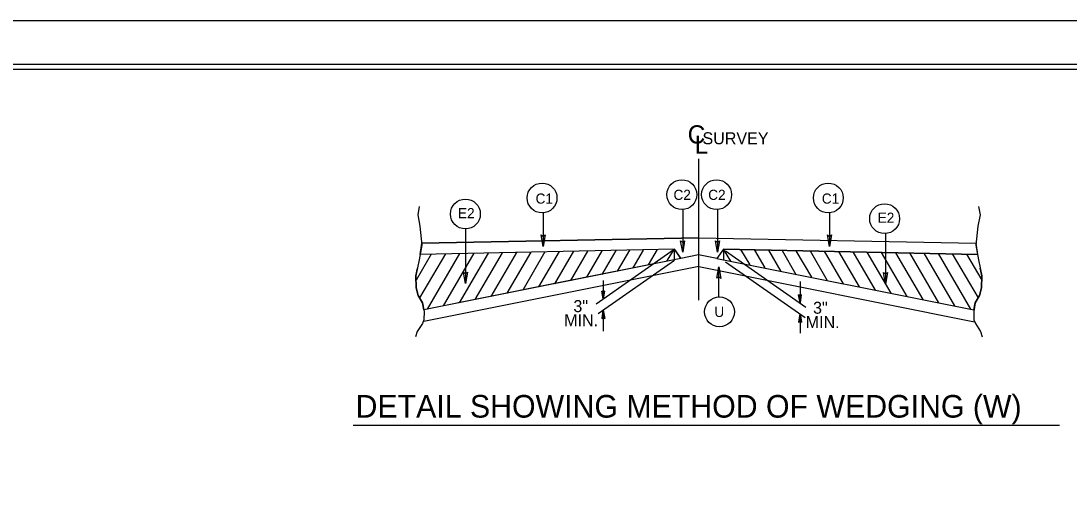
# Model space of a CAD drawing. Extents: x 1542177 to 1542464, y 45134 to 45344.
# Drawn here: x 1542284.79 to 1542327.96, y 45308.47 to 45328.62 of the extents above; entities that cross this region are included whole.
import ezdxf

# ---------------------------------------------------------------- set-up
doc = ezdxf.new("R2010")
doc.units = 0
for name, color, linetype in [('Prop Dimension', 7, 'Continuous'), ('Prop Dimension Text', 7, 'Continuous'), ('Sheet Cutting Line CELL', 7, 'Continuous'), ('Sheet Plot Border Inside CELL', 7, 'Continuous'), ('Sheet Plot Border Outside CELL', 7, 'Continuous'), ('Sheet Typical CELL', 7, 'Continuous'), ('Typical Detail Wedge2 CELL', 7, 'Continuous'), ('Typical ID Circle CELL', 7, 'Continuous'), ('Typical Terminator CELL', 7, 'Continuous'), ('Typical Text Centerline CELL', 7, 'Continuous'), ('Typical Text ID Circle CELL', 7, 'Continuous'), ('Typical Text Label CELL', 7, 'Continuous')]:
    doc.layers.add(name, color=color, linetype=linetype)

msp = doc.modelspace()

# ---------------------------------------------------------------- linework, layer by layer
at = {"layer": 'Prop Dimension'}
msp.add_line((1542312.711, 45317.117), (1542312.711, 45322.933), dxfattribs=at)
for centre in [(1542306.253, 45321.323), (1542312.011, 45321.459), (1542313.441, 45321.459), (1542318.042, 45321.323), (1542303.095, 45320.662), (1542320.361, 45320.47), (1542313.559, 45316.631)]:
    msp.add_circle(centre, 0.615, dxfattribs=at)
at = {"layer": 'Prop Dimension Text'}
msp.add_line((1542298.473, 45311.958), (1542327.56, 45311.958), dxfattribs=at)
at = {"layer": 'Sheet Cutting Line CELL'}
msp.add_line((1542360.727, 45328.616), (1542226.007, 45328.616), dxfattribs=at)
at = {"layer": 'Sheet Plot Border Inside CELL'}
msp.add_lwpolyline([(1542360.367, 45326.82), (1542227.047, 45326.82), (1542227.047, 45242.412), (1542360.367, 45242.412)], close=True, dxfattribs=at)
at = {"layer": 'Sheet Plot Border Outside CELL'}
for points in [[(1542360.727, 45328.616), (1542226.007, 45328.616), (1542226.007, 45240.616), (1542360.727, 45240.616)], [(1542360.727, 45328.615), (1542226.007, 45328.615), (1542226.007, 45240.616), (1542360.727, 45240.616)]]:
    msp.add_lwpolyline(points, close=True, dxfattribs=at)
at = {"layer": 'Sheet Typical CELL'}
msp.add_lwpolyline([(1542359.367, 45326.616), (1542239.367, 45326.616), (1542239.367, 45242.616), (1542359.367, 45242.616)], close=True, dxfattribs=at)
at = {"layer": 'Typical Detail Wedge2 CELL'}
for p, q in [((1542312.711, 45317.117), (1542312.711, 45321.089)), ((1542301.232, 45319), (1542301.297, 45319.458)), ((1542312.711, 45319.686), (1542301.297, 45319.458)), ((1542301.297, 45319.458), (1542312.711, 45319.686)), ((1542312.711, 45319.686), (1542324.125, 45319.458)), ((1542312.712, 45319.686), (1542324.125, 45319.458)), ((1542324.125, 45319.458), (1542324.191, 45319)), ((1542301.687, 45319.009), (1542301.063, 45317.939)), ((1542302.273, 45319.02), (1542301.212, 45317.203)), ((1542311.71, 45319.209), (1542301.232, 45319)), ((1542311.71, 45319.209), (1542301.232, 45319)), ((1542302.859, 45319.032), (1542301.523, 45316.743)), ((1542303.444, 45319.044), (1542302.178, 45316.874)), ((1542304.03, 45319.055), (1542302.833, 45317.005)), ((1542304.616, 45319.067), (1542303.489, 45317.136)), ((1542305.202, 45319.079), (1542304.144, 45317.267)), ((1542305.787, 45319.091), (1542304.8, 45317.398)), ((1542306.373, 45319.102), (1542305.455, 45317.529)), ((1542306.959, 45319.114), (1542306.111, 45317.66)), ((1542307.545, 45319.126), (1542306.766, 45317.792)), ((1542308.13, 45319.137), (1542307.422, 45317.923)), ((1542308.716, 45319.149), (1542308.077, 45318.054)), ((1542311.697, 45319.201), (1542308.481, 45316.948)), ((1542309.286, 45319.161), (1542308.712, 45318.175)), ((1542309.849, 45319.172), (1542309.346, 45318.308)), ((1542310.418, 45319.17), (1542309.99, 45318.439)), ((1542310.99, 45319.2), (1542310.618, 45318.562)), ((1542311.385, 45318.721), (1542311.695, 45319.205)), ((1542311.695, 45319.205), (1542311.695, 45318.807)), ((1542311.966, 45318.833), (1542311.71, 45319.209)), ((1542311.71, 45319.197), (1542311.966, 45318.833)), ((1542312.694, 45318.984), (1542311.966, 45318.833)), ((1542313.456, 45318.833), (1542312.694, 45318.984)), ((1542313.721, 45319.209), (1542313.456, 45318.833)), ((1542313.721, 45319.209), (1542313.456, 45318.833)), ((1542313.721, 45319.209), (1542324.191, 45319)), ((1542314.03, 45318.725), (1542313.721, 45319.209)), ((1542313.721, 45319.209), (1542313.721, 45318.779)), ((1542324.191, 45319), (1542313.721, 45319.209)), ((1542313.808, 45319.148), (1542317.121, 45316.828)), ((1542314.432, 45319.2), (1542314.804, 45318.562)), ((1542315.004, 45319.17), (1542315.432, 45318.439)), ((1542315.573, 45319.172), (1542316.088, 45318.288)), ((1542316.136, 45319.161), (1542316.711, 45318.175)), ((1542316.707, 45319.149), (1542317.345, 45318.054)), ((1542317.292, 45319.138), (1542318.001, 45317.923)), ((1542317.878, 45319.126), (1542318.656, 45317.792)), ((1542318.463, 45319.114), (1542319.311, 45317.661)), ((1542319.049, 45319.102), (1542319.966, 45317.53)), ((1542319.635, 45319.091), (1542320.622, 45317.398)), ((1542320.22, 45319.079), (1542321.277, 45317.267)), ((1542320.806, 45319.067), (1542321.932, 45317.136)), ((1542321.392, 45319.056), (1542322.587, 45317.005)), ((1542321.977, 45319.044), (1542323.242, 45316.874)), ((1542322.563, 45319.032), (1542323.898, 45316.743)), ((1542323.149, 45319.02), (1542324.209, 45317.202)), ((1542323.734, 45319.009), (1542324.359, 45317.937)), ((1542312.707, 45318.496), (1542301.379, 45316.23)), ((1542311.967, 45318.832), (1542301.383, 45316.715)), ((1542311.966, 45318.832), (1542306.569, 45317.752)), ((1542311.704, 45318.748), (1542308.557, 45316.544)), ((1542312.715, 45318.496), (1542324.07, 45316.225)), ((1542313.455, 45318.832), (1542324.04, 45316.715)), ((1542313.455, 45318.832), (1542324.04, 45316.715)), ((1542313.803, 45318.697), (1542317.084, 45316.4)), ((1542308.076, 45318.054), (1542307.718, 45317.982)), ((1542306.569, 45317.752), (1542301.383, 45316.715)), ((1542308.774, 45317.919), (1542308.774, 45317.154)), ((1542316.879, 45317.875), (1542316.879, 45316.998)), ((1542308.774, 45317.154), (1542308.714, 45317.489)), ((1542308.774, 45317.445), (1542308.714, 45317.489)), ((1542308.774, 45317.154), (1542308.723, 45317.483)), ((1542308.731, 45317.476), (1542308.774, 45317.154)), ((1542308.774, 45317.154), (1542308.74, 45317.471)), ((1542308.748, 45317.464), (1542308.774, 45317.154)), ((1542308.774, 45317.154), (1542308.757, 45317.458)), ((1542308.765, 45317.452), (1542308.774, 45317.154)), ((1542308.774, 45317.154), (1542308.833, 45317.489)), ((1542308.833, 45317.489), (1542308.774, 45317.445)), ((1542308.825, 45317.483), (1542308.774, 45317.154)), ((1542308.774, 45317.154), (1542308.816, 45317.476)), ((1542308.807, 45317.471), (1542308.774, 45317.154)), ((1542308.774, 45317.154), (1542308.799, 45317.464)), ((1542308.79, 45317.458), (1542308.774, 45317.154)), ((1542308.774, 45317.154), (1542308.782, 45317.452)), ((1542308.774, 45317.445), (1542308.774, 45317.154)), ((1542316.879, 45316.998), (1542316.82, 45317.333)), ((1542316.879, 45317.29), (1542316.82, 45317.333)), ((1542316.879, 45316.998), (1542316.828, 45317.327)), ((1542316.837, 45317.321), (1542316.879, 45316.998)), ((1542316.879, 45316.998), (1542316.845, 45317.314)), ((1542316.854, 45317.308), (1542316.879, 45316.998)), ((1542316.879, 45316.998), (1542316.862, 45317.302)), ((1542316.87, 45317.296), (1542316.879, 45316.998)), ((1542316.879, 45316.998), (1542316.938, 45317.333)), ((1542316.938, 45317.333), (1542316.879, 45317.29)), ((1542316.93, 45317.327), (1542316.879, 45316.998)), ((1542316.879, 45316.998), (1542316.921, 45317.321)), ((1542316.913, 45317.314), (1542316.879, 45316.998)), ((1542316.879, 45316.998), (1542316.904, 45317.308)), ((1542316.896, 45317.302), (1542316.879, 45316.998)), ((1542316.879, 45316.998), (1542316.888, 45317.296)), ((1542316.879, 45317.29), (1542316.879, 45316.998)), ((1542308.774, 45316.696), (1542308.714, 45316.36)), ((1542308.714, 45316.36), (1542308.774, 45316.404)), ((1542308.723, 45316.367), (1542308.774, 45316.696)), ((1542308.774, 45316.696), (1542308.731, 45316.373)), ((1542308.74, 45316.379), (1542308.774, 45316.696)), ((1542308.774, 45316.696), (1542308.748, 45316.385)), ((1542308.757, 45316.391), (1542308.774, 45316.696)), ((1542308.774, 45316.696), (1542308.765, 45316.397)), ((1542308.774, 45316.696), (1542308.774, 45315.834)), ((1542308.774, 45316.696), (1542308.833, 45316.36)), ((1542308.774, 45316.404), (1542308.774, 45316.696)), ((1542308.782, 45316.397), (1542308.774, 45316.696)), ((1542308.774, 45316.696), (1542308.79, 45316.391)), ((1542308.799, 45316.385), (1542308.774, 45316.696)), ((1542308.774, 45316.696), (1542308.807, 45316.379)), ((1542308.816, 45316.373), (1542308.774, 45316.696)), ((1542308.774, 45316.696), (1542308.825, 45316.367)), ((1542308.774, 45316.404), (1542308.833, 45316.36)), ((1542316.879, 45316.544), (1542316.82, 45316.208)), ((1542316.828, 45316.215), (1542316.879, 45316.544)), ((1542316.879, 45316.544), (1542316.837, 45316.221)), ((1542316.845, 45316.227), (1542316.879, 45316.544)), ((1542316.879, 45316.544), (1542316.854, 45316.233)), ((1542316.862, 45316.239), (1542316.879, 45316.544)), ((1542316.879, 45316.544), (1542316.87, 45316.245)), ((1542316.879, 45316.544), (1542316.879, 45315.759)), ((1542316.879, 45316.544), (1542316.938, 45316.208)), ((1542316.879, 45316.252), (1542316.879, 45316.544)), ((1542316.888, 45316.245), (1542316.879, 45316.544)), ((1542316.879, 45316.544), (1542316.896, 45316.239)), ((1542316.904, 45316.233), (1542316.879, 45316.544)), ((1542316.879, 45316.544), (1542316.913, 45316.227)), ((1542316.921, 45316.221), (1542316.879, 45316.544)), ((1542316.879, 45316.544), (1542316.93, 45316.215)), ((1542316.82, 45316.208), (1542316.879, 45316.252)), ((1542316.879, 45316.252), (1542316.938, 45316.208))]:
    msp.add_line(p, q, dxfattribs=at)
for points in [[(1542301.191, 45320.965), (1542301.13, 45320.63), (1542301.221, 45320.155), (1542301.302, 45319.385), (1542301.191, 45318.778), (1542301.059, 45318.12), (1542301.07, 45317.623), (1542301.151, 45317.31), (1542301.333, 45316.996), (1542301.393, 45316.651), (1542301.383, 45316.307), (1542301.323, 45316.145), (1542301.11, 45315.821), (1542301.039, 45315.598)], [(1542324.231, 45320.965), (1542324.292, 45320.63), (1542324.201, 45320.155), (1542324.12, 45319.385), (1542324.231, 45318.778), (1542324.363, 45318.12), (1542324.353, 45317.623), (1542324.271, 45317.31), (1542324.089, 45316.996), (1542324.029, 45316.651), (1542324.039, 45316.307), (1542324.099, 45316.145), (1542324.312, 45315.821), (1542324.383, 45315.598)], [(1542301.382, 45316.715), (1542301.333, 45316.996), (1542301.151, 45317.31), (1542301.07, 45317.623), (1542301.059, 45318.12), (1542301.12, 45318.425)], [(1542324.04, 45316.715), (1542324.089, 45316.996), (1542324.271, 45317.31), (1542324.353, 45317.623), (1542324.363, 45318.12), (1542324.302, 45318.425)]]:
    msp.add_lwpolyline(points, dxfattribs=at)
at = {"layer": 'Typical ID Circle CELL'}
for p, q in [((1542306.301, 45320.709), (1542306.301, 45319.327)), ((1542312.045, 45320.845), (1542312.045, 45319.085)), ((1542313.475, 45320.845), (1542313.475, 45319.085)), ((1542318.089, 45320.709), (1542318.089, 45319.327)), ((1542303.098, 45320.047), (1542303.098, 45317.796)), ((1542320.393, 45319.856), (1542320.393, 45317.778)), ((1542313.537, 45317.246), (1542313.537, 45318.485))]:
    msp.add_line(p, q, dxfattribs=at)
at = {"layer": 'Typical Terminator CELL'}
for points in [[(1542306.382, 45319.799), (1542306.301, 45319.327), (1542306.217, 45319.802), (1542306.301, 45319.742)], [(1542318.171, 45319.799), (1542318.089, 45319.327), (1542318.006, 45319.802), (1542318.089, 45319.742)], [(1542312.126, 45319.557), (1542312.045, 45319.085), (1542311.961, 45319.56), (1542312.045, 45319.499)], [(1542313.556, 45319.557), (1542313.475, 45319.085), (1542313.391, 45319.56), (1542313.475, 45319.499)], [(1542313.456, 45318.013), (1542313.537, 45318.485), (1542313.621, 45318.01), (1542313.537, 45318.07)], [(1542303.179, 45318.268), (1542303.098, 45317.796), (1542303.014, 45318.27), (1542303.098, 45318.21)], [(1542320.475, 45318.25), (1542320.393, 45317.778), (1542320.31, 45318.253), (1542320.393, 45318.192)]]:
    msp.add_lwpolyline(points, close=True, dxfattribs=at)

# ---------------------------------------------------------------- texts
at = {"layer": 'Typical Detail Wedge2 CELL'}
for s, p in [('3"', (1542307.543, 45316.619)), ('3"', (1542317.415, 45316.553)), ('MIN.', (1542307.162, 45316.037)), ('MIN.', (1542317.111, 45315.962))]:
    msp.add_text(s, height=0.495, rotation=360, dxfattribs=at).set_placement(p)
at = {"layer": 'Typical Text Centerline CELL'}
for s, height, rotation, p in [('C', 0.752, 0, (1542312.25, 45323.565)), ('L', 0.752, 0, (1542312.536, 45323.143)), (' SURVEY ', 0.495, 360, (1542312.675, 45323.535))]:
    msp.add_text(s, height=height, rotation=rotation, dxfattribs=at).set_placement(p)
at = {"layer": 'Typical Text ID Circle CELL'}
for s, height, p in [('C1', 0.4184, (1542305.987, 45321.089)), ('C2', 0.4184, (1542311.666, 45321.243)), ('C2', 0.4184, (1542313.096, 45321.243)), ('C1', 0.4184, (1542317.776, 45321.089)), ('E2', 0.4184, (1542302.79, 45320.488)), ('E2', 0.4184, (1542320.077, 45320.301)), ('U', 0.418, (1542313.351, 45316.42))]:
    msp.add_text(s, height=height, rotation=360, dxfattribs=at).set_placement(p)
at = {"layer": 'Typical Text Label CELL'}
msp.add_text('DETAIL SHOWING METHOD OF WEDGING (W)', height=0.93247, rotation=360, dxfattribs=at).set_placement((1542298.572, 45312.273))

doc.saveas('drawing.dxf')
